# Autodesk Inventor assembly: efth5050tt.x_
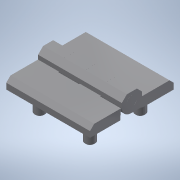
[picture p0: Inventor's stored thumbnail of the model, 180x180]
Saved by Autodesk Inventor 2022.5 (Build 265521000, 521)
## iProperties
Part Number: efth5050tt.x_
Material: 一般
Document SubType Name: Assembly
Designer: ImaoCorp
Sending System: SOLIDWORKS 2017-2017317
MC: AMD64
MC_MODEL: Intel64 Family 6 Model 60 Stepping 3, GenuineIntel
OS: Windows_NT
FRU: Parasolid Version 29.0, build 201,  4-17-2017
FORMAT: text
GUISE: transmit
KEY: efth5050tt
FILE: efth5050tt.x_t
DATE: Mon May 13 14:22:11 2019
Author: ImaoCorp
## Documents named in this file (4)
- X:\14_SW2022-Inv2022\00_全2023-1023新製品(TCC)まで\e\efth5050tt\EFTH5050TT.iam
- X:\14_SW2022-Inv2022\00_全2023-1023新製品(TCC)まで\e\efth5050tt\efth5050tt_01.ipt
- X:\14_SW2022-Inv2022\00_全2023-1023新製品(TCC)まで\e\efth5050tt\efth5050tt_02.ipt
- X:\14_SW2022-Inv2022\00_全2023-1023新製品(TCC)まで\e\efth5050tt\efth5050tt_03.ipt
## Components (3 placed, 3 different names)
1. efth5050tt_01
2. efth5050tt_02
3. efth5050tt_03
